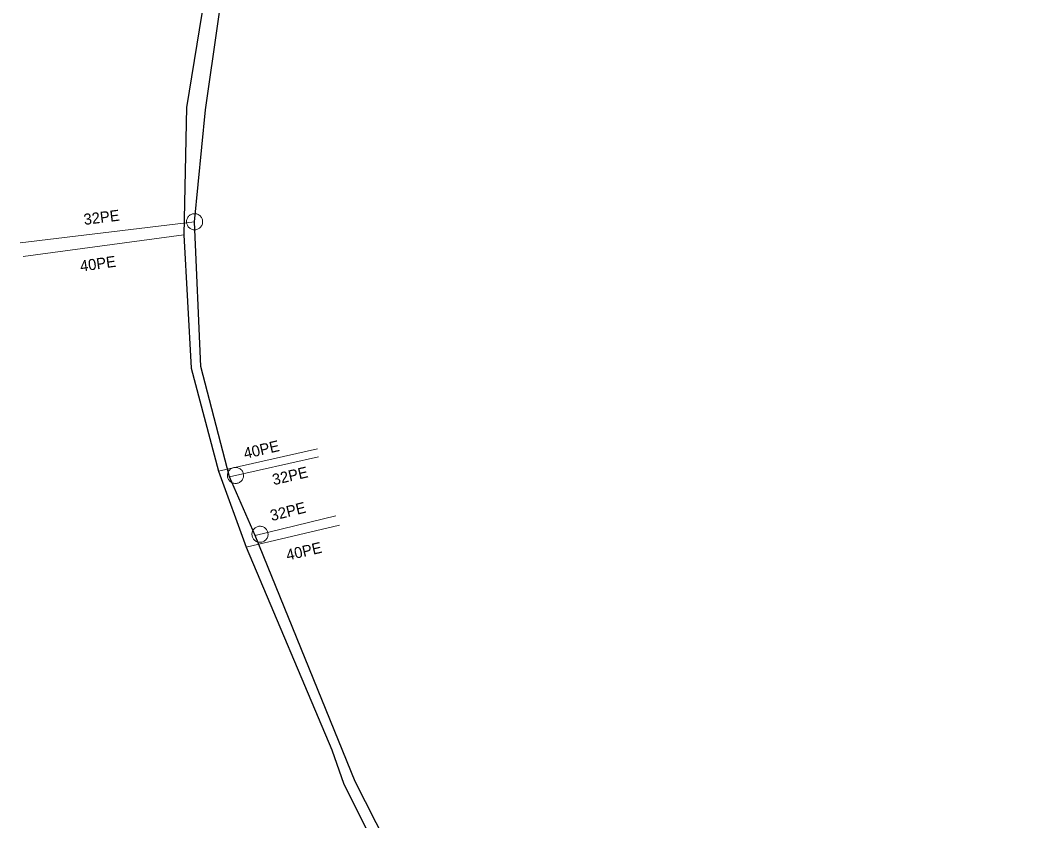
# Model space of a CAD drawing. Extents: x -741806 to -738704, y -1059275 to -1055387.
# Drawn here: x -740317.8 to -740262.8, y -1057178.6 to -1057135.1 of the extents above; entities that cross this region are included whole.
import ezdxf

# ---------------------------------------------------------------- set-up
doc = ezdxf.new("R2010")
doc.units = 0
doc.header["$LTSCALE"] = 0.4
for name, color, linetype, lineweight in [('2', 7, 'Continuous', 25), ('21', 7, 'Continuous', 13), ('51', 7, 'Continuous', 13), ('52', 7, 'Continuous', 25), ('56', 7, 'Continuous', 13)]:
    doc.layers.add(name, color=color, linetype=linetype, lineweight=lineweight)
doc.layers.add('54', color=7, linetype='Continuous')
doc.layers.add('55', color=7, linetype='Continuous')

msp = doc.modelspace()

# ---------------------------------------------------------------- linework, layer by layer
at = {"layer": '2'}
msp.add_lwpolyline([(-740262.96, -1057069.909), (-740269.19, -1057072.669), (-740274.949, -1057077.7), (-740275.559, -1057078.32), (-740280.173, -1057082.526), (-740281.937, -1057084.151), (-740283.887, -1057086.098), (-740285.828, -1057088.145), (-740287.55, -1057089.96), (-740294.199, -1057098.5), (-740299.28, -1057106.06), (-740302.629, -1057112.73), (-740305.219, -1057120.72), (-740306.46, -1057125.389), (-740308.809, -1057139.85), (-740308.96, -1057146.77), (-740308.55, -1057154.01), (-740307.079, -1057159.62), (-740305.57, -1057163.75), (-740300.92, -1057174.76), (-740300.27, -1057176.629), (-740296.46, -1057184.19), (-740290.177, -1057193.486), (-740285.949, -1057197.84)], dxfattribs=at)
at = {"layer": '21'}
for p, q in [((-740308.37, -1057146.06), (-740317.84, -1057147.2)), ((-740306.469, -1057159.919), (-740301.64, -1057158.83)), ((-740305.079, -1057163.11), (-740300.69, -1057162.04))]:
    msp.add_line(p, q, dxfattribs=at)
at = {"layer": '51'}
for points in [[(-740308.388, -1057145.623), (-740308.433, -1057145.627), (-740308.477, -1057145.636), (-740308.522, -1057145.65), (-740308.563, -1057145.667), (-740308.603, -1057145.69), (-740308.641, -1057145.717), (-740308.675, -1057145.747), (-740308.706, -1057145.781), (-740308.733, -1057145.818), (-740308.756, -1057145.857), (-740308.775, -1057145.899), (-740308.79, -1057145.943), (-740308.801, -1057145.987), (-740308.806, -1057146.032), (-740308.806, -1057146.078), (-740308.802, -1057146.124), (-740308.793, -1057146.169), (-740308.779, -1057146.212), (-740308.76, -1057146.255), (-740308.737, -1057146.295), (-740308.711, -1057146.331), (-740308.681, -1057146.366), (-740308.647, -1057146.397), (-740308.61, -1057146.424), (-740308.57, -1057146.448), (-740308.529, -1057146.467), (-740308.486, -1057146.481), (-740308.44, -1057146.491), (-740308.395, -1057146.496), (-740308.349, -1057146.497), (-740308.304, -1057146.492), (-740308.26, -1057146.483), (-740308.215, -1057146.469), (-740308.174, -1057146.451), (-740308.134, -1057146.429), (-740308.096, -1057146.402), (-740308.062, -1057146.372), (-740308.031, -1057146.338), (-740308.004, -1057146.301), (-740307.981, -1057146.262), (-740307.962, -1057146.22), (-740307.947, -1057146.176), (-740307.937, -1057146.132), (-740307.931, -1057146.087), (-740307.931, -1057146.041), (-740307.935, -1057145.995), (-740307.945, -1057145.95), (-740307.958, -1057145.907), (-740307.977, -1057145.864), (-740308, -1057145.824), (-740308.026, -1057145.787), (-740308.056, -1057145.753), (-740308.09, -1057145.722), (-740308.127, -1057145.695), (-740308.167, -1057145.671), (-740308.208, -1057145.652), (-740308.251, -1057145.638), (-740308.297, -1057145.628), (-740308.342, -1057145.623), (-740308.387, -1057145.623)], [(-740305.722, -1057159.751), (-740305.734, -1057159.707), (-740305.751, -1057159.665), (-740305.772, -1057159.624), (-740305.797, -1057159.586), (-740305.827, -1057159.551), (-740305.86, -1057159.518), (-740305.896, -1057159.491), (-740305.934, -1057159.465), (-740305.975, -1057159.446), (-740306.018, -1057159.43), (-740306.063, -1057159.419), (-740306.108, -1057159.411), (-740306.154, -1057159.409), (-740306.199, -1057159.413), (-740306.245, -1057159.421), (-740306.289, -1057159.433), (-740306.331, -1057159.45), (-740306.372, -1057159.471), (-740306.41, -1057159.497), (-740306.445, -1057159.526), (-740306.477, -1057159.559), (-740306.506, -1057159.594), (-740306.53, -1057159.634), (-740306.55, -1057159.674), (-740306.566, -1057159.718), (-740306.578, -1057159.762), (-740306.584, -1057159.807), (-740306.586, -1057159.853), (-740306.583, -1057159.899), (-740306.575, -1057159.944), (-740306.563, -1057159.988), (-740306.546, -1057160.03), (-740306.524, -1057160.071), (-740306.499, -1057160.109), (-740306.47, -1057160.144), (-740306.437, -1057160.177), (-740306.401, -1057160.204), (-740306.362, -1057160.229), (-740306.321, -1057160.249), (-740306.279, -1057160.265), (-740306.234, -1057160.276), (-740306.188, -1057160.283), (-740306.143, -1057160.285), (-740306.097, -1057160.282), (-740306.052, -1057160.274), (-740306.008, -1057160.262), (-740305.965, -1057160.244), (-740305.925, -1057160.224), (-740305.887, -1057160.198), (-740305.851, -1057160.168), (-740305.82, -1057160.136), (-740305.791, -1057160.1), (-740305.767, -1057160.061), (-740305.746, -1057160.021), (-740305.73, -1057159.977), (-740305.719, -1057159.933), (-740305.713, -1057159.888), (-740305.711, -1057159.842), (-740305.714, -1057159.796), (-740305.722, -1057159.752)]]:
    msp.add_lwpolyline(points, dxfattribs=at)
msp.add_lwpolyline([(-740304.392, -1057162.943), (-740304.404, -1057162.899), (-740304.422, -1057162.857), (-740304.444, -1057162.816), (-740304.47, -1057162.779), (-740304.5, -1057162.744), (-740304.533, -1057162.712), (-740304.57, -1057162.685), (-740304.609, -1057162.661), (-740304.65, -1057162.642), (-740304.693, -1057162.627), (-740304.738, -1057162.616), (-740304.784, -1057162.61), (-740304.829, -1057162.609), (-740304.875, -1057162.612), (-740304.92, -1057162.621), (-740304.964, -1057162.634), (-740305.006, -1057162.652), (-740305.046, -1057162.674), (-740305.084, -1057162.7), (-740305.119, -1057162.731), (-740305.15, -1057162.764), (-740305.178, -1057162.8), (-740305.201, -1057162.839), (-740305.221, -1057162.88), (-740305.236, -1057162.924), (-740305.247, -1057162.969), (-740305.253, -1057163.013), (-740305.254, -1057163.06), (-740305.25, -1057163.105), (-740305.242, -1057163.151), (-740305.228, -1057163.194), (-740305.211, -1057163.236), (-740305.188, -1057163.277), (-740305.163, -1057163.314), (-740305.133, -1057163.349), (-740305.099, -1057163.38), (-740305.063, -1057163.408), (-740305.024, -1057163.432), (-740304.982, -1057163.451), (-740304.939, -1057163.466), (-740304.895, -1057163.477), (-740304.849, -1057163.483), (-740304.803, -1057163.483), (-740304.758, -1057163.48), (-740304.713, -1057163.472), (-740304.668, -1057163.459), (-740304.627, -1057163.44), (-740304.586, -1057163.419), (-740304.549, -1057163.392), (-740304.514, -1057163.362), (-740304.483, -1057163.329), (-740304.455, -1057163.293), (-740304.431, -1057163.254), (-740304.411, -1057163.213), (-740304.396, -1057163.169), (-740304.386, -1057163.124), (-740304.38, -1057163.08), (-740304.379, -1057163.033), (-740304.383, -1057162.988)], close=True, dxfattribs=at)
at = {"layer": '52'}
msp.add_lwpolyline([(-740283.129, -1057198.97), (-740283.26, -1057198.81), (-740289.74, -1057192.772), (-740295.66, -1057184.32), (-740299.64, -1057176.48), (-740305.079, -1057163.11), (-740306.469, -1057159.919), (-740308.03, -1057153.929), (-740308.37, -1057146.06), (-740307.77, -1057139.98), (-740305.71, -1057125.55), (-740304.82, -1057121.77), (-740302.16, -1057112.889), (-740299.12, -1057106.889), (-740298.43, -1057105.73), (-740293.78, -1057098.919), (-740287, -1057090.56), (-740282.309, -1057085.5), (-740278.449, -1057081.76), (-740275.899, -1057079.48), (-740275.289, -1057078.97), (-740268.949, -1057073.48), (-740263.329, -1057070.639), (-740262.78, -1057070.48)], dxfattribs=at)
at = {"layer": '56'}
for p, q in [((-740317.68, -1057147.94), (-740308.96, -1057146.77)), ((-740301.69, -1057158.409), (-740307.079, -1057159.62)), ((-740300.489, -1057162.55), (-740305.57, -1057163.75))]:
    msp.add_line(p, q, dxfattribs=at)

# ---------------------------------------------------------------- texts
at = {"layer": '54'}
for rotation, p in [(7, (-740314.36, -1057146.235)), (13, (-740304.074, -1057160.38)), (14, (-740304.178, -1057162.332))]:
    msp.add_text('32PE', height=0.6, rotation=rotation, dxfattribs=at).set_placement(p)
at = {"layer": '55'}
for rotation, p in [(8, (-740314.552, -1057148.773)), (13, (-740305.628, -1057158.954)), (13, (-740303.32, -1057164.479))]:
    msp.add_text('40PE', height=0.6, rotation=rotation, dxfattribs=at).set_placement(p)

doc.saveas('drawing.dxf')
